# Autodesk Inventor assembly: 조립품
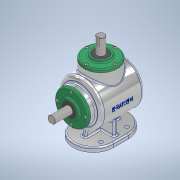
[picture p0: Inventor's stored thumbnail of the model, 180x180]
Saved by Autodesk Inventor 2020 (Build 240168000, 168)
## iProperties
Created: 2023-01
Part Number: 조립품
Document SubType Name: Assembly
Designer: home
Author: home
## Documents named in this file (14)
- C:\Users\home\Desktop\730106V1003\조립품.iam
- C:\Users\home\Desktop\730106V1003\본체.ipt
- C:\Users\home\Desktop\730106V1003\공용\서브 축.ipt
- 서브 축.ipt
- C:\Users\home\Desktop\730106V1003\공용\커버.ipt
- C:\Users\home\Desktop\730106V1003\공용\오일실 17 32 8.ipt
- C:\Users\home\Desktop\730106V1003\공용\베어링 6203.ipt
- C:\Users\home\Desktop\730106V1003\공용\키 4x4.ipt
- C:\Users\home\Desktop\730106V1003\공용\서브 베벨기어.ipt
- C:\Users\home\Desktop\730106V1003\공용\메인 축.ipt
- 메인 축.ipt
- C:\Users\home\Desktop\730106V1003\공용\메인 베벨기어.ipt
- C:\Users\home\Desktop\730106V1003\공용\키 5x5.ipt
- C:\Users\home\Desktop\730106V1003\공용\M4.ipt
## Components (8 placed, 1 different names)
1. M4:1 — Insert:11
2. M4:3
3. M4:4
4. M4:5
5. M4:2 — Insert:12
6. M4:6
7. M4:7
8. M4:8
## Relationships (2: Insert 2)
- Insert:11: M4:1
- Insert:12: M4:2
